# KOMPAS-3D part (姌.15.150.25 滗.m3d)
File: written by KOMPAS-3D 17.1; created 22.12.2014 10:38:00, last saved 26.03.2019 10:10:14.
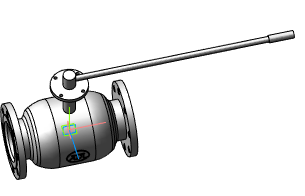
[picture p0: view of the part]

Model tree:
1. Операция без истории:6  (labels: Сталь 20  ГОСТ 1050-88)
